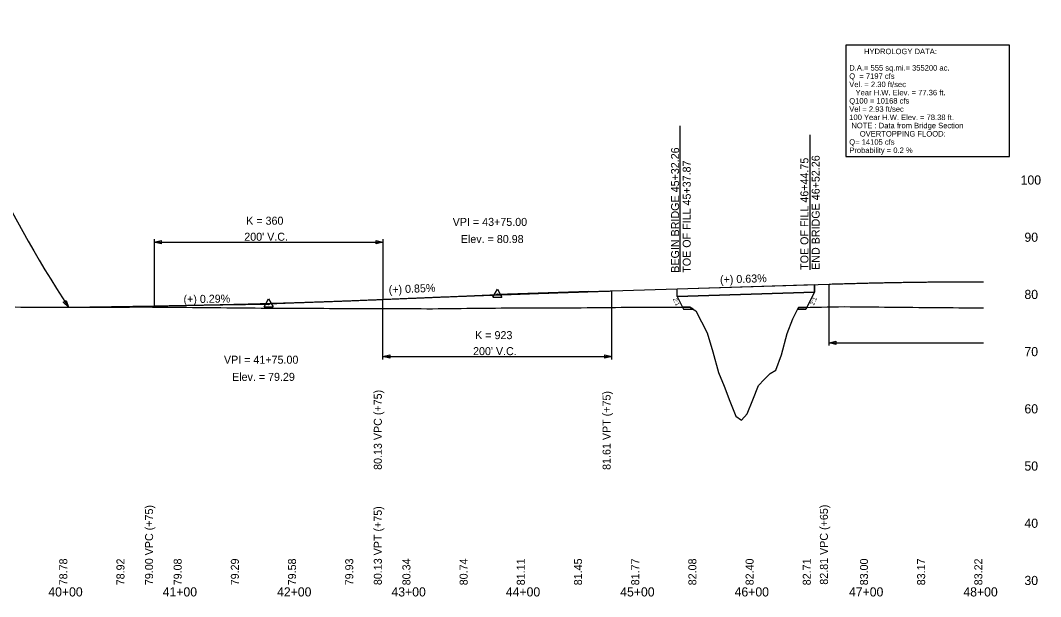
# Model space of a CAD drawing. Extents: x -3336 to 3318, y -3606 to 6276.
# Drawn here: x 683 to 1575, y -509 to -5 of the extents above; entities that cross this region are included whole.
import ezdxf

# ---------------------------------------------------------------- set-up
doc = ezdxf.new("R2010")
doc.units = 0
for name, color, linetype in [('RD_DDB_ElevTX', 7, 'Continuous'), ('RD_DDB_GradeTX', 7, 'Continuous'), ('RD_DDB_Profile_EX', 7, 'Continuous'), ('RD_DDB_Profile_Lbl', 7, 'Continuous'), ('RD_DDB_Profile_PR', 7, 'Continuous'), ('RD_DDB_StaTX', 7, 'Continuous'), ('RD_DDB_StripGrade', 7, 'Continuous'), ('RD_DDB_VCLbl', 7, 'Continuous'), ('RD_HC_Data', 7, 'Continuous'), ('RD_PD_Final_TX', 7, 'Continuous'), ('RD_TX_Drainage', 7, 'Continuous'), ('RD_TX_Profile', 7, 'Continuous'), ('RD_XS_TieSlope', 7, 'Continuous')]:
    doc.layers.add(name, color=color, linetype=linetype)

msp = doc.modelspace()

# ---------------------------------------------------------------- linework, layer by layer
at = {"layer": 'RD_DDB_GradeTX'}
for p, q in [((1020.07, -248.48), (1100, -245.1)), ((1179.96, -242.58), (1100, -245.1)), ((820.01, -254.72), (900, -253.56)), ((979.93, -250.18), (900, -253.56))]:
    msp.add_line(p, q, dxfattribs=at)
at = {"layer": 'RD_DDB_Profile_EX'}
for points in [[(678.38, -255.92), (683.38, -256.01), (688.38, -256.09), (693.38, -256.14), (698.38, -256.13), (703.38, -256.12), (708.38, -256.11), (713.38, -256.11), (718.38, -256.1), (723.38, -256.09), (728.38, -256.08), (733.38, -256.07), (738.38, -256.07), (743.38, -256.06), (748.38, -256.05), (753.38, -256.04), (758.38, -256.03), (763.38, -256.03), (768.38, -256.02), (773.38, -256.01), (778.38, -256), (783.38, -255.99), (788.38, -255.99), (793.38, -255.98), (798.38, -256.01), (803.38, -256.05), (808.38, -256.1), (813.38, -256.14), (818.38, -256.19), (823.38, -256.24), (828.38, -256.28), (833.38, -256.33), (838.38, -256.38), (843.38, -256.43), (848.38, -256.48), (853.38, -256.52), (858.38, -256.57), (863.38, -256.62), (868.38, -256.67), (873.38, -256.72), (878.38, -256.76), (883.38, -256.81), (888.38, -256.86), (893.38, -256.91), (898.38, -256.94), (903.38, -256.96), (908.38, -256.98), (913.38, -256.99), (918.38, -257.02), (923.38, -257.04)], [(923.38, -257.04), (928.38, -257.06), (933.38, -257.08), (938.38, -257.11), (943.38, -257.13), (948.38, -257.15), (953.38, -257.17), (958.38, -257.19), (963.38, -257.22), (968.38, -257.23), (973.38, -257.25), (978.38, -257.28), (983.38, -257.3), (988.38, -257.32), (993.38, -257.33), (998.38, -257.34), (1003.38, -257.36), (1008.38, -257.38), (1013.38, -257.39), (1018.38, -257.41), (1023.38, -257.42), (1028.38, -257.44), (1033.38, -257.45), (1038.38, -257.47), (1043.38, -257.48), (1048.38, -257.42), (1053.38, -257.37), (1058.38, -257.31), (1063.38, -257.25), (1068.38, -257.19), (1073.38, -257.13), (1078.38, -257.08), (1083.38, -257.02), (1088.38, -256.96), (1093.38, -256.91), (1098.38, -256.88), (1103.38, -256.85), (1108.38, -256.83), (1113.38, -256.8), (1118.38, -256.78), (1123.38, -256.77), (1128.38, -256.76), (1133.38, -256.75), (1138.38, -256.74), (1143.38, -256.74), (1148.38, -256.73), (1153.38, -256.73), (1158.38, -256.74), (1163.38, -256.75), (1168.38, -256.67), (1173.38, -256.61), (1178.38, -256.55), (1183.38, -256.5), (1188.38, -256.45), (1193.38, -256.4), (1198.38, -256.35), (1203.38, -256.3), (1208.38, -256.26), (1213.38, -256.21), (1218.38, -256.17), (1223.38, -256.16), (1228.38, -256.14), (1233.38, -256.13), (1238.38, -256.11), (1243.38, -256.1), (1248.38, -256.11), (1253.38, -256.09), (1258.38, -256.08), (1263.38, -256.07), (1268.38, -256.06), (1273.38, -259.4), (1278.38, -269.01), (1283.38, -278.62), (1288.38, -295.11), (1293.38, -313.39), (1298.38, -325.27), (1303.38, -338.31), (1308.38, -351.34), (1313.38, -354.86), (1318.38, -349.34), (1323.38, -337.22), (1328.38, -324.53), (1333.38, -319.4), (1338.38, -314.26), (1343.38, -311.12), (1348.38, -297.72), (1353.38, -279.12), (1358.38, -266.27), (1363.38, -256.43), (1368.38, -256.34), (1373.38, -256.25), (1378.38, -256.15), (1383.38, -256.08), (1388.38, -255.99), (1393.38, -255.89), (1398.38, -255.8), (1403.38, -255.7), (1408.38, -255.71), (1413.38, -255.76), (1418.38, -255.8), (1423.38, -255.85)], [(1423.38, -255.85), (1428.38, -255.9), (1433.38, -255.95), (1438.38, -256), (1443.38, -256.05), (1448.38, -256.09), (1453.38, -256.14), (1458.38, -256.19), (1463.38, -256.24), (1468.38, -256.29), (1473.38, -256.33), (1478.38, -256.38), (1483.38, -256.43), (1488.38, -256.48), (1493.38, -256.53), (1498.38, -256.57), (1503.38, -256.62), (1508.38, -256.65), (1513.38, -256.66), (1518.38, -256.66), (1523.38, -256.67), (1525, -256.67)]]:
    msp.add_lwpolyline(points, dxfattribs=at)
at = {"layer": 'RD_DDB_Profile_PR'}
for p, q in [((1200, -241.95), (1390, -235.97)), ((1257.26, -246.8), (1257.26, -240.15)), ((1377.26, -243.03), (1377.26, -236.37)), ((1257.26, -246.8), (1377.26, -243.03)), ((725, -256.1), (800, -255.01))]:
    msp.add_line(p, q, dxfattribs=at)
msp.add_lwpolyline([(1257.26, -246.8), (1257.26, -240.15), (1377.26, -236.37), (1377.26, -243.03)], close=True, dxfattribs=at)
for points in [[(1390, -235.97), (1392.7, -235.89), (1395.4, -235.81), (1398.1, -235.72), (1400.8, -235.65), (1403.5, -235.57), (1406.2, -235.49), (1408.9, -235.42), (1411.6, -235.35), (1414.3, -235.28), (1417, -235.21), (1419.7, -235.14), (1422.4, -235.08), (1425.1, -235.01), (1427.8, -234.95), (1430.5, -234.89), (1433.2, -234.83), (1435.9, -234.78), (1438.6, -234.72), (1441.3, -234.67), (1444, -234.62), (1446.7, -234.57), (1449.4, -234.52), (1452.1, -234.48), (1454.8, -234.43), (1457.5, -234.39), (1460.2, -234.35), (1462.9, -234.31), (1465.6, -234.27), (1468.3, -234.24), (1471, -234.21), (1473.7, -234.17), (1476.4, -234.14), (1479.1, -234.12), (1481.8, -234.09), (1484.5, -234.06), (1487.2, -234.04), (1489.9, -234.02), (1492.6, -234), (1495.3, -233.98), (1498, -233.97), (1500.7, -233.95), (1503.4, -233.94), (1506.1, -233.93), (1508.8, -233.92), (1511.5, -233.91), (1514.2, -233.9), (1516.9, -233.9), (1519.6, -233.9), (1522.3, -233.9), (1525, -233.9)], [(800, -255.01), (804, -254.95), (808, -254.89), (812, -254.83), (816, -254.76), (820, -254.69), (824, -254.62), (828, -254.55), (832, -254.48), (836, -254.4), (840, -254.32), (844, -254.24), (848, -254.16), (852, -254.07), (856, -253.98), (860, -253.89), (864, -253.8), (868, -253.7), (872, -253.61), (876, -253.51), (880, -253.41), (884, -253.3), (888, -253.2), (892, -253.09), (896, -252.98), (900, -252.87), (904, -252.75), (908, -252.64), (912, -252.52), (916, -252.39), (920, -252.27), (924, -252.15), (928, -252.02), (932, -251.89), (936, -251.75), (940, -251.62), (944, -251.48), (948, -251.34), (952, -251.2), (956, -251.06), (960, -250.91), (964, -250.76), (968, -250.61), (972, -250.46), (976, -250.31), (980, -250.15), (984, -249.99), (988, -249.83), (992, -249.67), (996, -249.5), (1000, -249.33)], [(1000, -249.33), (1004, -249.16), (1008, -248.99), (1012, -248.83), (1016, -248.66), (1020, -248.5), (1024, -248.33), (1028, -248.17), (1032, -248), (1036, -247.84), (1040, -247.68), (1044, -247.52), (1048, -247.36), (1052, -247.2), (1056, -247.05), (1060, -246.89), (1064, -246.73), (1068, -246.58), (1072, -246.43), (1076, -246.27), (1080, -246.12), (1084, -245.97), (1088, -245.82), (1092, -245.67), (1096, -245.52), (1100, -245.37), (1104, -245.22), (1108, -245.08), (1112, -244.93), (1116, -244.79), (1120, -244.64), (1124, -244.5), (1128, -244.36), (1132, -244.22), (1136, -244.08), (1140, -243.94), (1144, -243.8), (1148, -243.66), (1152, -243.53), (1156, -243.39), (1160, -243.25), (1164, -243.12), (1168, -242.99), (1172, -242.85), (1176, -242.72), (1180, -242.59), (1184, -242.46), (1188, -242.33), (1192, -242.21), (1196, -242.08), (1200, -241.95)]]:
    msp.add_spline(points, degree=3, dxfattribs=at)
at = {"layer": 'RD_DDB_StripGrade'}
for p, q in [((1259.81, -225.25), (1259.81, -97.6)), ((1373.41, -223.55), (1373.41, -105.49)), ((1261.89, -256.08), (1262.87, -258)), ((1262.87, -258), (1271.29, -258)), ((1362.58, -258), (1369.75, -258)), ((1369.75, -258), (1370.61, -256.3)), ((1370.61, -256.3), (1370.61, -256.3))]:
    msp.add_line(p, q, dxfattribs=at)
for points in [[(1271.29, -258), (1268.38, -256.06), (1263.38, -256.07), (1261.89, -256.08)], [(1370.61, -256.3), (1368.38, -256.34), (1363.38, -256.43), (1362.58, -258)]]:
    msp.add_lwpolyline(points, dxfattribs=at)
at = {"layer": 'RD_DDB_VCLbl'}
for p, q in [((800, -196.83), (800, -255.01)), ((800, -199.33), (1000, -199.33)), ((1000, -196.83), (1000, -249.33)), ((1390, -289.78), (1390, -235.97)), ((1000, -301.83), (1000, -249.33)), ((1200, -301.83), (1200, -241.95)), ((1390, -287.28), (1525, -287.28)), ((1000, -299.33), (1200, -299.33))]:
    msp.add_line(p, q, dxfattribs=at)
at = {"layer": 'RD_HC_Data'}
for p, q in [((1096.03, -247.39), (1100, -240.51)), ((1100, -240.51), (1103.97, -247.39)), ((896.03, -255.87), (900, -248.99)), ((900, -248.99), (903.97, -255.87)), ((1096.03, -247.39), (1103.97, -247.39)), ((896.03, -255.87), (903.97, -255.87))]:
    msp.add_line(p, q, dxfattribs=at)
for centre in [(1100, -245.1), (900, -253.58)]:
    msp.add_circle(centre, 0.529, dxfattribs=at)
at = {"layer": 'RD_PD_Final_TX'}
msp.add_arc((1633.55, 337.29), 1085.16, 196.85399, 213.14949, dxfattribs=at)
at = {"layer": 'RD_TX_Drainage'}
for points in [[(806, -200.83), (800, -199.33), (806, -197.83)], [(994, -197.83), (1000, -199.33), (994, -200.83)], [(722.97, -250.26), (725, -256.1), (720.46, -251.9)], [(1396, -288.78), (1390, -287.28), (1396, -285.78)], [(1006, -300.83), (1000, -299.33), (1006, -297.83)], [(1194, -297.83), (1200, -299.33), (1194, -300.83)]]:
    msp.add_lwpolyline(points, close=True, dxfattribs=at)
at = {"layer": 'RD_TX_Profile'}
msp.add_lwpolyline([(1404.65, -124.44), (1547.82, -124.44), (1547.82, -27.19), (1404.65, -27.19)], close=True, dxfattribs=at)
at = {"layer": 'RD_XS_TieSlope'}
for p, q in [((1257.26, -246.8), (1262.87, -258)), ((1377.26, -243.03), (1369.75, -258))]:
    msp.add_line(p, q, dxfattribs=at)

# ---------------------------------------------------------------- texts
at = {"layer": 'RD_DDB_ElevTX'}
for s, p in [('100', (1557.5, -149)), ('90', (1560.81, -199)), ('80', (1560.81, -249)), ('70', (1560.81, -299)), ('60', (1560.81, -349)), ('50', (1560.81, -399)), ('40', (1560.81, -449)), ('30', (1560.81, -499))]:
    msp.add_text(s, height=8, dxfattribs=at).set_placement(p)
at = {"layer": 'RD_DDB_GradeTX'}
for s, rotation, p in [('(+) 0.63%', 1.80292, (1294.74, -235.54)), ('(+) 0.85%', 2.42288, (1005.14, -244.37)), ('(+) 0.29%', 0.83073, (825.65, -252.64))]:
    msp.add_text(s, height=7, rotation=rotation, dxfattribs=at).set_placement(p)
at = {"layer": 'RD_DDB_Profile_Lbl'}
for s, p in [('VPI = 43+75.00', (1060.97, -185.1)), ('Elev. = 80.98', (1068.05, -200.1)), ('VPI = 41+75.00', (860.97, -305.56)), ('Elev. = 79.29', (868.05, -320.56))]:
    msp.add_text(s, height=7, dxfattribs=at).set_placement(p)
at = {"layer": 'RD_DDB_StaTX'}
for s, p in [('40+00', (707.41, -509)), ('41+00', (807.41, -509)), ('42+00', (907.41, -509)), ('43+00', (1007.41, -509)), ('44+00', (1107.41, -509)), ('45+00', (1207.41, -509)), ('46+00', (1307.41, -509)), ('47+00', (1407.41, -509)), ('48+00', (1507.41, -509))]:
    msp.add_text(s, height=8, dxfattribs=at).set_placement(p)
at = {"layer": 'RD_DDB_StripGrade'}
for s, p in [('BEGIN BRIDGE 45+32.26', (1258.87, -226.04)), ('END BRIDGE 46+52.26', (1381.78, -223.55)), ('TOE OF FILL 45+37.87 ', (1269.04, -226.04)), ('TOE OF FILL 46+44.75', (1371.94, -223.55)), ('80.13 VPC (+75)', (999, -398.38)), ('81.61 VPT (+75)', (1199, -398.38)), ('79.00 VPC (+75)', (799, -499.07)), ('80.13 VPT (+75)', (999, -499.07)), ('82.81 VPC (+65)', (1389, -498.72)), ('78.78', (724, -499.25)), ('78.92', (774, -499.25)), ('79.08', (824, -499.25)), ('79.29', (874, -499.25)), ('79.58', (924, -499.25)), ('79.93', (974, -499.25)), ('80.34', (1024, -499.25)), ('80.74', (1074, -499.25)), ('81.11', (1124, -499.25)), ('81.45', (1174, -499.25)), ('81.77', (1224, -499.25)), ('82.08', (1274, -499.25)), ('82.40', (1324, -499.25)), ('82.71', (1374, -499.25)), ('83.00', (1424, -499.25)), ('83.17', (1474, -499.25)), ('83.22', (1524, -499.25))]:
    msp.add_text(s, height=7, rotation=90, dxfattribs=at).set_placement(p)
at = {"layer": 'RD_DDB_VCLbl'}
for s, p in [('K = 360', (880.44, -184.08)), ("200' V.C.", (878.75, -198.08)), ('K = 923', (1080.6, -284.08)), ("200' V.C.", (1078.75, -298.08))]:
    msp.add_text(s, height=7, dxfattribs=at).set_placement(p)
for rotation, p in [(293.62274, (1253.41, -248.96)), (66.37726, (1376.71, -254.82))]:
    msp.add_text('2:1', height=3.72, rotation=rotation, dxfattribs=at).set_placement(p)
at = {"layer": 'RD_TX_Profile'}
for s, p in [('       HYDROLOGY DATA:', (1407.65, -34.99)), ('D.A.= 555 sq.mi.= 355200 ac.', (1407.65, -49.39)), ('Q  = 7197 cfs', (1407.65, -56.59)), ('Vel. = 2.30 ft/sec', (1407.65, -63.79)), ('   Year H.W. Elev. = 77.36 ft.', (1407.65, -70.99)), ('Q100 = 10168 cfs', (1407.65, -78.19)), ('Vel = 2.93 ft/sec', (1407.65, -85.39)), ('100 Year H.W. Elev. = 78.38 ft.', (1407.65, -92.59)), (' NOTE : Data from Bridge Section', (1407.65, -99.79)), ('     OVERTOPPING FLOOD:', (1407.65, -106.99)), ('Q= 14105 cfs', (1407.65, -114.19)), ('Probability = 0.2 %', (1407.65, -121.39))]:
    msp.add_text(s, height=4.8, dxfattribs=at).set_placement(p)

doc.saveas('drawing.dxf')
